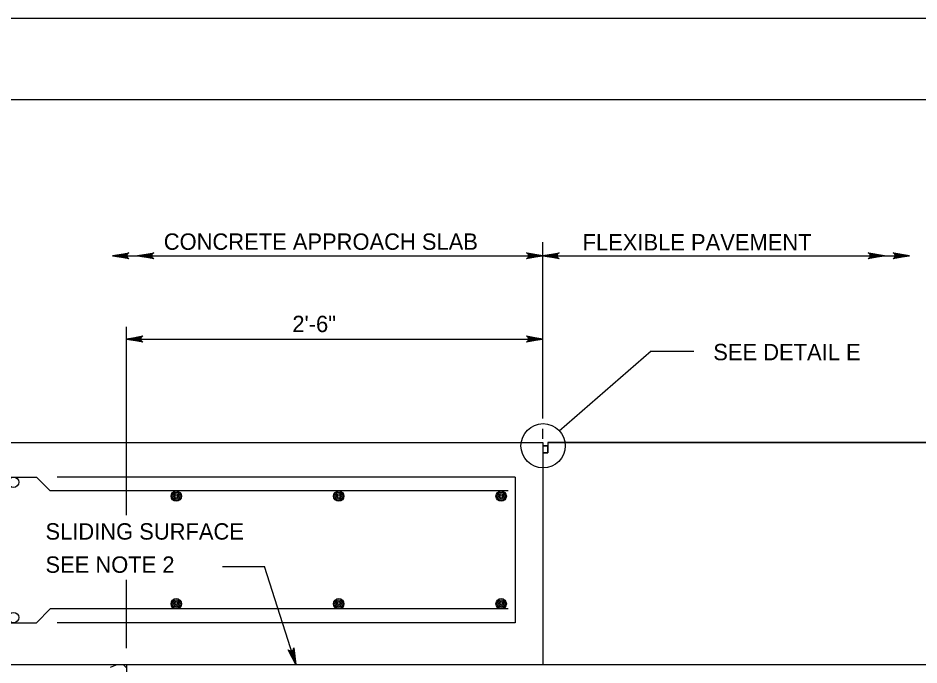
# Model space of a CAD drawing. Extents: x 638079 to 640019, y 297691 to 298879.
# Drawn here: x 639245.9 to 639410.8, y 298760.8 to 298879.2 of the extents above; entities that cross this region are included whole.
import ezdxf

# ---------------------------------------------------------------- set-up
doc = ezdxf.new("R2010")
doc.units = 0
doc.layers.add('1', color=7, linetype='Continuous')
doc.layers.add('PLT-BNDY', color=7, linetype='Continuous')

msp = doc.modelspace()

# ---------------------------------------------------------------- linework, layer by layer
at = {"layer": '1'}
for p, q in [((639341.94, 298805.97), (639341.94, 298838.21)), ((639263.19, 298835.73), (639341.94, 298835.73)), ((639341.94, 298835.73), (639409.05, 298835.73)), ((639265.74, 298788.26), (639265.74, 298822.71)), ((639265.74, 298820.49), (639341.94, 298820.49)), ((639361.75, 298818.28), (639344.94, 298803.61)), ((639361.75, 298818.28), (639369.61, 298818.28)), ((639341.94, 298802.23), (639341.94, 298804.06)), ((639199.6, 298801.58), (639341.94, 298801.58)), ((639341.94, 298801.58), (639341.94, 298760.94)), ((639342.89, 298801.58), (639493.43, 298801.58)), ((639342.89, 298801.58), (639342.89, 298799.67)), ((639341.94, 298800.94), (639342.89, 298800.94)), ((639341.94, 298799.67), (639342.89, 298799.67)), ((639199.6, 298795.23), (639249.23, 298795.23)), ((639251.77, 298792.69), (639249.23, 298795.23)), ((639336.86, 298795.23), (639253.04, 298795.23)), ((639336.86, 298795.23), (639336.86, 298768.56)), ((639335.59, 298792.69), (639251.77, 298792.69)), ((639283.3, 298778.84), (639291.01, 298778.84)), ((639296.74, 298760.94), (639291.01, 298778.84)), ((639265.74, 298763.91), (639265.74, 298776.41)), ((639251.77, 298771.1), (639249.23, 298768.56)), ((639335.59, 298771.1), (639251.77, 298771.1)), ((639199.6, 298768.56), (639249.23, 298768.56)), ((639336.86, 298768.56), (639253.04, 298768.56)), ((639199.6, 298760.94), (639341.94, 298760.94)), ((639265.74, 298760.94), (639418.14, 298760.94)), ((639265.74, 298760.94), (639265.74, 298730.46))]:
    msp.add_line(p, q, dxfattribs=at)
for points in [[(639940.03, 298300.23), (639940.03, 298864.23), (639154.03, 298864.23), (639154.03, 298300.23), (639940.03, 298300.23), (639940.03, 298326.59), (639740.03, 298326.59), (639740.03, 298391.26), (639940.03, 298391.26), (639940.03, 298420.23), (639740.03, 298420.23), (639740.03, 298300.23), (639818.83, 298300.23), (639818.83, 298326.59), (639818.83, 298300.23), (639895.83, 298300.23), (639895.83, 298326.59), (639895.83, 298314.27), (639940.03, 298314.27)], [(639263.19, 298835.73), (639266.17, 298836.29), (639266.05, 298836.21), (639265.94, 298836.13), (639265.88, 298836.03), (639265.82, 298835.93), (639265.8, 298835.83), (639265.79, 298835.73), (639265.8, 298835.63), (639265.82, 298835.53), (639265.88, 298835.43), (639265.94, 298835.33), (639266.05, 298835.26), (639266.17, 298835.18), (639263.19, 298835.73), (639266.05, 298835.26), (639265.94, 298835.33), (639263.19, 298835.73), (639265.88, 298835.43), (639265.82, 298835.53), (639263.19, 298835.73), (639265.8, 298835.63), (639265.79, 298835.73), (639263.19, 298835.73), (639265.8, 298835.83), (639265.82, 298835.93), (639263.19, 298835.73), (639265.88, 298836.03), (639265.94, 298836.13), (639263.19, 298835.73), (639266.05, 298836.21)], [(639267.76, 298835.73), (639270.74, 298836.29), (639270.63, 298836.21), (639270.51, 298836.13), (639270.45, 298836.03), (639270.39, 298835.93), (639270.37, 298835.83), (639270.36, 298835.73), (639270.37, 298835.63), (639270.39, 298835.53), (639270.45, 298835.43), (639270.51, 298835.33), (639270.63, 298835.26), (639270.74, 298835.18), (639267.76, 298835.73), (639270.63, 298835.26), (639270.51, 298835.33), (639267.76, 298835.73), (639270.45, 298835.43), (639270.39, 298835.53), (639267.76, 298835.73), (639270.37, 298835.63), (639270.36, 298835.73), (639267.76, 298835.73), (639270.37, 298835.83), (639270.39, 298835.93), (639267.76, 298835.73), (639270.45, 298836.03), (639270.51, 298836.13), (639267.76, 298835.73), (639270.63, 298836.21)], [(639341.94, 298835.73), (639338.96, 298835.18), (639339.07, 298835.26), (639339.19, 298835.33), (639339.25, 298835.43), (639339.31, 298835.53), (639339.32, 298835.63), (639339.34, 298835.73), (639339.32, 298835.83), (639339.31, 298835.93), (639339.25, 298836.03), (639339.19, 298836.13), (639339.07, 298836.21), (639338.96, 298836.29), (639341.94, 298835.73), (639339.07, 298836.21), (639339.19, 298836.13), (639341.94, 298835.73), (639339.25, 298836.03), (639339.31, 298835.93), (639341.94, 298835.73), (639339.32, 298835.83), (639339.34, 298835.73), (639341.94, 298835.73), (639339.32, 298835.63), (639339.31, 298835.53), (639341.94, 298835.73), (639339.25, 298835.43), (639339.19, 298835.33), (639341.94, 298835.73), (639339.07, 298835.26)], [(639341.94, 298835.73), (639344.92, 298836.29), (639344.81, 298836.21), (639344.69, 298836.13), (639344.63, 298836.03), (639344.57, 298835.93), (639344.56, 298835.83), (639344.54, 298835.73), (639344.56, 298835.63), (639344.57, 298835.53), (639344.63, 298835.43), (639344.69, 298835.33), (639344.81, 298835.26), (639344.92, 298835.18), (639341.94, 298835.73), (639344.81, 298835.26), (639344.69, 298835.33), (639341.94, 298835.73), (639344.63, 298835.43), (639344.57, 298835.53), (639341.94, 298835.73), (639344.56, 298835.63), (639344.54, 298835.73), (639341.94, 298835.73), (639344.56, 298835.83), (639344.57, 298835.93), (639341.94, 298835.73), (639344.63, 298836.03), (639344.69, 298836.13), (639341.94, 298835.73), (639344.81, 298836.21)], [(639404.48, 298835.73), (639401.5, 298835.18), (639401.61, 298835.26), (639401.73, 298835.33), (639401.79, 298835.43), (639401.85, 298835.53), (639401.86, 298835.63), (639401.88, 298835.73), (639401.86, 298835.83), (639401.85, 298835.93), (639401.79, 298836.03), (639401.73, 298836.13), (639401.61, 298836.21), (639401.5, 298836.29), (639404.48, 298835.73), (639401.61, 298836.21), (639401.73, 298836.13), (639404.48, 298835.73), (639401.79, 298836.03), (639401.85, 298835.93), (639404.48, 298835.73), (639401.86, 298835.83), (639401.88, 298835.73), (639404.48, 298835.73), (639401.86, 298835.63), (639401.85, 298835.53), (639404.48, 298835.73), (639401.79, 298835.43), (639401.73, 298835.33), (639404.48, 298835.73), (639401.61, 298835.26)], [(639409.05, 298835.73), (639406.07, 298835.18), (639406.19, 298835.26), (639406.3, 298835.33), (639406.36, 298835.43), (639406.42, 298835.53), (639406.44, 298835.63), (639406.45, 298835.73), (639406.44, 298835.83), (639406.42, 298835.93), (639406.36, 298836.03), (639406.3, 298836.13), (639406.19, 298836.21), (639406.07, 298836.29), (639409.05, 298835.73), (639406.19, 298836.21), (639406.3, 298836.13), (639409.05, 298835.73), (639406.36, 298836.03), (639406.42, 298835.93), (639409.05, 298835.73), (639406.44, 298835.83), (639406.45, 298835.73), (639409.05, 298835.73), (639406.44, 298835.63), (639406.42, 298835.53), (639409.05, 298835.73), (639406.36, 298835.43), (639406.3, 298835.33), (639409.05, 298835.73), (639406.19, 298835.26)], [(639265.74, 298820.49), (639268.72, 298821.05), (639268.61, 298820.97), (639268.49, 298820.89), (639268.43, 298820.79), (639268.37, 298820.69), (639268.36, 298820.59), (639268.34, 298820.49), (639268.36, 298820.39), (639268.37, 298820.29), (639268.43, 298820.19), (639268.49, 298820.09), (639268.61, 298820.02), (639268.72, 298819.94), (639265.74, 298820.49), (639268.61, 298820.02), (639268.49, 298820.09), (639265.74, 298820.49), (639268.43, 298820.19), (639268.37, 298820.29), (639265.74, 298820.49), (639268.36, 298820.39), (639268.34, 298820.49), (639265.74, 298820.49), (639268.36, 298820.59), (639268.37, 298820.69), (639265.74, 298820.49), (639268.43, 298820.79), (639268.49, 298820.89), (639265.74, 298820.49), (639268.61, 298820.97)], [(639341.94, 298820.49), (639338.96, 298819.94), (639339.07, 298820.02), (639339.19, 298820.09), (639339.25, 298820.19), (639339.31, 298820.29), (639339.32, 298820.39), (639339.34, 298820.49), (639339.32, 298820.59), (639339.31, 298820.69), (639339.25, 298820.79), (639339.19, 298820.89), (639339.07, 298820.97), (639338.96, 298821.05), (639341.94, 298820.49), (639339.07, 298820.97), (639339.19, 298820.89), (639341.94, 298820.49), (639339.25, 298820.79), (639339.31, 298820.69), (639341.94, 298820.49), (639339.32, 298820.59), (639339.34, 298820.49), (639341.94, 298820.49), (639339.32, 298820.39), (639339.31, 298820.29), (639341.94, 298820.49), (639339.25, 298820.19), (639339.19, 298820.09), (639341.94, 298820.49), (639339.07, 298820.02)], [(639296.74, 298760.94), (639295.3, 298763.61), (639295.41, 298763.52), (639295.52, 298763.44), (639295.63, 298763.41), (639295.75, 298763.38), (639295.85, 298763.4), (639295.95, 298763.41), (639296.04, 298763.46), (639296.13, 298763.51), (639296.21, 298763.59), (639296.28, 298763.68), (639296.32, 298763.81), (639296.36, 298763.95), (639296.74, 298760.94), (639296.32, 298763.81), (639296.28, 298763.68), (639296.74, 298760.94), (639296.21, 298763.59), (639296.13, 298763.51), (639296.74, 298760.94), (639296.04, 298763.46), (639295.95, 298763.41), (639296.74, 298760.94), (639295.85, 298763.4), (639295.75, 298763.38), (639296.74, 298760.94), (639295.63, 298763.41), (639295.52, 298763.44), (639296.74, 298760.94), (639295.41, 298763.52)], [(639262.78, 298760.44), (639264.04, 298760.94)], [(639264.04, 298760.94), (639265.19, 298760.84), (639265.74, 298760.31)]]:
    msp.add_lwpolyline(points, dxfattribs=at)
for points in [[(639488.26, 298789.41), (639493.43, 298791.95), (639493.43, 298801.58), (639342.89, 298801.58), (639342.89, 298799.67), (639341.94, 298799.67), (639341.94, 298760.94), (639418.14, 298760.94), (639438.46, 298781.25), (639493.43, 298781.25), (639493.43, 298788.43), (639498.39, 298790.78)], [(639341.94, 298799.67), (639342.89, 298799.67), (639342.89, 298800.94), (639341.94, 298800.94)]]:
    msp.add_lwpolyline(points, close=True, dxfattribs=at)
for centre, radius in [((639341.99, 298800.95), 4.05), ((639245.06, 298794.28), 0.952), ((639274.83, 298791.74), 0.952), ((639274.83, 298791.74), 0.714), ((639274.83, 298791.74), 0.476), ((639274.83, 298791.74), 0.238), ((639304.59, 298791.74), 0.952), ((639304.59, 298791.74), 0.714), ((639304.59, 298791.74), 0.476), ((639304.59, 298791.74), 0.238), ((639334.32, 298791.74), 0.952), ((639334.32, 298791.74), 0.714), ((639334.32, 298791.74), 0.476), ((639334.32, 298791.74), 0.238), ((639274.83, 298772.05), 0.952), ((639274.83, 298772.05), 0.714), ((639274.83, 298772.05), 0.476), ((639274.83, 298772.05), 0.238), ((639304.59, 298772.05), 0.952), ((639304.59, 298772.05), 0.714), ((639304.59, 298772.05), 0.476), ((639304.59, 298772.05), 0.238), ((639334.32, 298772.05), 0.952), ((639334.32, 298772.05), 0.714), ((639334.32, 298772.05), 0.476), ((639334.32, 298772.05), 0.238), ((639245.06, 298769.51), 0.952)]:
    msp.add_circle(centre, radius, dxfattribs=at)
at = {"layer": 'PLT-BNDY'}
msp.add_lwpolyline([(639115.03, 298879.23), (639956.03, 298879.23), (639956.03, 298285.23), (639115.03, 298285.23)], close=True, dxfattribs=at)

# ---------------------------------------------------------------- texts
at = {"layer": '1'}
for s, p in [('CONCRETE APPROACH SLAB', (639272.55, 298836.81)), ('FLEXIBLE PAVEMENT', (639349.23, 298836.7)), ('2\'-6"', (639296.09, 298821.75)), ('SEE DETAIL E', (639373.15, 298816.6)), ('SLIDING SURFACE', (639250.89, 298783.78)), ('SEE NOTE 2', (639250.89, 298777.71))]:
    msp.add_text(s, height=3, dxfattribs=at).set_placement(p)

doc.saveas('drawing.dxf')
